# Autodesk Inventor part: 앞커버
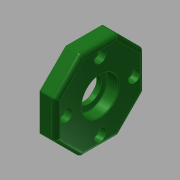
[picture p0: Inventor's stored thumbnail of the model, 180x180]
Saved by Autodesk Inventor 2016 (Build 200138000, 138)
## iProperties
Created: 2015-11
Part Number: 앞커버
Material: 알루미늄 6061
Document SubType Name: Modeling
Designer: mduedu
Density: 1 g/cm^3
Appearance: 매끄러움 - 짙은 산림 녹색
Author: mduedu
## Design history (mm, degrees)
sketch "스케치5" dims "d66" = 60
  geometry: L1 (12.426, 30)-(30, 12.426); L2 (30, 12.426)-(30, -12.426); L3 (30, -12.426)-(12.426, -30); L4 (12.426, -30)-(-12.426, -30); L5 (-12.426, -30)-(-30, -12.426); L6 (-30, -12.426)-(-30, 12.426); L7 (-30, 12.426)-(-12.426, 30); L8 (-12.426, 30)-(12.426, 30); 4 further points
  constraints: 16 end point, 2 coincident, 2 vertical alignment, 1 midpoint, 19 other
extrude "돌출2" new body sketch "스케치5" distance "d67" = 11; taper "d68" = 0 deg
sketch "스케치6"
  geometry: C1 r 16 at (0, 0); 1 further point
  constraints: 1 centre point, 1 coincident
  dimensions: "d69" = 32 diameter of C1
extrude "돌출3" join sketch "스케치6" distance "d70" = 3; taper "d71" = 0 deg
hole "구멍7" diameter "d98" = 25; stored, may be unused: countersink angle "d102" = 90 deg, drill point angle "d104" = 0 deg; dims "d96" = 10, "d97" = 10, "d99" = 6, "d100" = 4, "d101" = 2, "d103" = 3
hole "구멍8" diameter "d107" = 25; stored, may be unused: countersink angle "d111" = 90 deg, drill point angle "d113" = 0 deg; dims "d105" = 10, "d106" = 10, "d108" = 6, "d109" = 4, "d110" = 2, "d112" = 7.7
hole "구멍9" diameter "d116" = 17; stored, may be unused: countersink angle "d120" = 90 deg, drill point angle "d122" = 0 deg; dims "d114" = 10, "d115" = 10, "d117" = 6, "d118" = 4, "d119" = 2, "d121" = 7.7
chamfer "모따기2" distance "d123" = 0.6; stored, may be unused: second distance "d124" = 2, angle "d125" = 30 deg
fillet "모깎기11" dims "d126" = 0.3
fillet "모깎기12" dims "d127" = 1
fillet "모깎기13" dims "d128" = 3
fillet "모깎기14" dims "d129" = 3
fillet "모깎기15" dims "d130" = 0.3
sketch "스케치8" dims "d131" = 46
  geometry: 3 further points
  constraints: 2 vertical alignment, 1 coincident, 2 other
hole "구멍10" sketch "스케치8" at (0, 23) diameter "d132" = 4.5; stored, may be unused: countersink angle "d136" = 90 deg, drill point angle "d138" = 0 deg; dims "d133" = 6, "d134" = 8, "d135" = 4.6, "d137" = 7.7
node "솔리드2"
pattern_circular "원형 패턴4" dims angle "d140" = 360 deg
